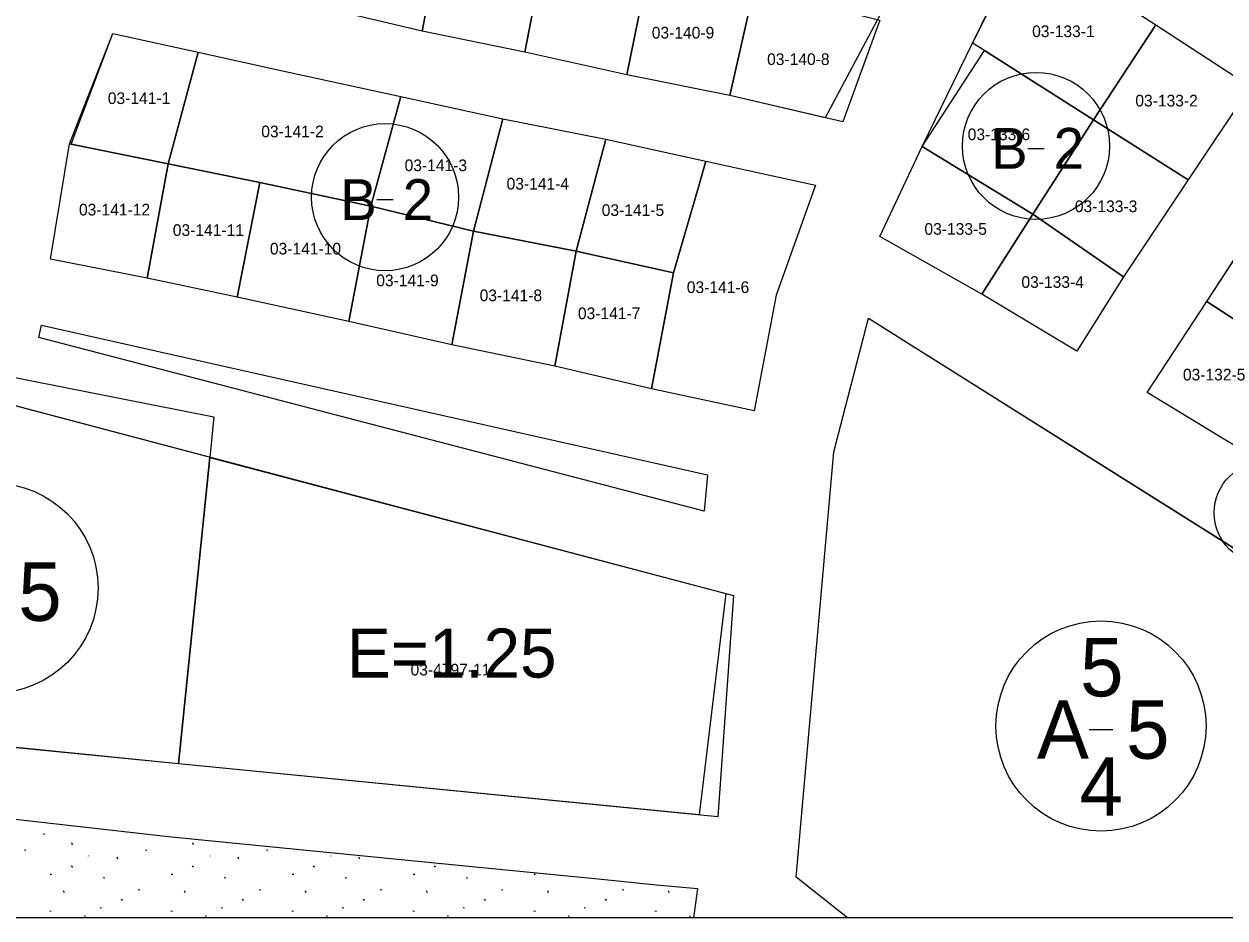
# Model space of a CAD drawing. Extents: x 413946 to 415528, y 4453939 to 4454944.
# Drawn here: x 414871.3 to 414974.2, y 4453939.5 to 4454016.1 of the extents above; entities that cross this region are included whole.
import ezdxf

# ---------------------------------------------------------------- set-up
doc = ezdxf.new("R2010")
doc.units = 0
for name, color, linetype in [('0_KADASTRO', 7, 'Continuous'), ('0_ÇERÇEVE', 7, 'Continuous'), ('Level 27', 7, 'Continuous'), ('Level 28', 7, 'Continuous'), ('Level 41', 7, 'Continuous'), ('Level 54', 7, 'Continuous'), ('Level 62', 7, 'Continuous'), ('SEMBOL', 7, 'Continuous')]:
    doc.layers.add(name, color=color, linetype=linetype)

msp = doc.modelspace()

# ---------------------------------------------------------------- linework, layer by layer
at = {"layer": '0_KADASTRO'}
for points in [[(414896.58, 4454017.51), (414898.64, 4454028.11), (414900.43, 4454027.65), (414907.43, 4454025.87), (414905.42, 4454015.45)], [(414905.42, 4454015.45), (414907.43, 4454025.87), (414909.43, 4454025.36), (414916.17, 4454023.65), (414914.21, 4454013.64)], [(414914.21, 4454013.64), (414916.17, 4454023.65), (414918.06, 4454023.17), (414924.92, 4454021.42), (414922.95, 4454011.69)], [(414952.58, 4454014.42), (414956.96, 4454023.35), (414968.29, 4454015.97), (414962.95, 4454007.85), (414953.6, 4454013.78)], [(414922.95, 4454011.69), (414924.92, 4454021.42), (414926.87, 4454020.92), (414933.86, 4454019.14), (414931.8, 4454009.93)], [(414931.8, 4454009.93), (414933.86, 4454019.14), (414935.82, 4454018.64), (414944.64, 4454016.39), (414941.47, 4454007.67)], [(414962.95, 4454007.85), (414968.29, 4454015.97), (414976.39, 4454010.71), (414971.06, 4454002.71)], [(414875.35, 4454005.76), (414878.91, 4454015.23), (414886.23, 4454013.64), (414883.67, 4454004.08)], [(414883.67, 4454004.08), (414886.23, 4454013.64), (414893.45, 4454012.04), (414903.6, 4454009.83), (414901.03, 4454000.45), (414891.51, 4454002.49)], [(414948.26, 4454005.56), (414953.6, 4454013.78), (414962.95, 4454007.85), (414957.76, 4453999.76)], [(414901.03, 4454000.45), (414903.6, 4454009.83), (414912.33, 4454007.92), (414909.83, 4453998.32)], [(414909.83, 4453998.32), (414912.33, 4454007.92), (414921.15, 4454006.18), (414918.63, 4453996.59)], [(414957.76, 4453999.76), (414962.95, 4454007.85), (414971.06, 4454002.71), (414965.53, 4453994.41)], [(414873.59, 4453995.9), (414875.22, 4454005.78), (414875.35, 4454005.76), (414883.67, 4454004.08), (414881.86, 4453994.27)], [(414918.63, 4453996.59), (414921.15, 4454006.18), (414929.73, 4454004.3), (414929.06, 4454001.99), (414926.97, 4453994.75)], [(414944.65, 4453997.84), (414948.26, 4454005.56), (414957.76, 4453999.76), (414953.37, 4453992.92)], [(414881.86, 4453994.27), (414883.67, 4454004.08), (414891.51, 4454002.49), (414889.57, 4453992.65)], [(414925.08, 4453984.8), (414926.97, 4453994.75), (414929.06, 4454001.99), (414929.73, 4454004.3), (414939.12, 4454002.24), (414935.76, 4453992.82), (414933.86, 4453982.93)], [(414889.57, 4453992.65), (414891.51, 4454002.49), (414901.03, 4454000.45), (414899.15, 4453990.57)], [(414899.15, 4453990.57), (414901.03, 4454000.45), (414909.83, 4453998.32), (414907.96, 4453988.58)], [(414953.37, 4453992.92), (414957.76, 4453999.76), (414965.53, 4453994.41), (414961.52, 4453988.03)], [(414972.65, 4453992.28), (414976.98, 4453998.9), (414984.98, 4453993.76), (414980.63, 4453987.09)], [(414907.96, 4453988.58), (414909.83, 4453998.32), (414918.63, 4453996.59), (414916.78, 4453986.75)], [(414916.78, 4453986.75), (414918.63, 4453996.59), (414926.97, 4453994.75), (414925.08, 4453984.8)], [(414967.55, 4453984.5), (414972.65, 4453992.28), (414980.63, 4453987.09), (414975.77, 4453979.48)], [(414847.64, 4453956.4), (414847.89, 4453969.56), (414848.25, 4453989.16), (414848.27, 4453990.17), (414887.57, 4453982.39), (414887.22, 4453978.91), (414884.55, 4453952.69)], [(414884.55, 4453952.69), (414887.22, 4453978.91), (414932.09, 4453967.11), (414930.77, 4453948.14)]]:
    msp.add_lwpolyline(points, close=True, dxfattribs=at)
for points in [[(414941.88, 4453939.48), (414937.48, 4453942.98), (414940.69, 4453979.42), (414943.68, 4453990.85), (415025.26, 4453939.48)], [(415025.26, 4453939.48), (414941.88, 4453939.48)]]:
    msp.add_lwpolyline(points, dxfattribs=at)
at = {"layer": '0_ÇERÇEVE'}
msp.add_lwpolyline([(413945.57, 4454943.96), (415494.14, 4454943.96), (415494.14, 4453939.48), (413945.57, 4453939.48)], close=True, dxfattribs=at)
at = {"layer": 'Level 27'}
for p, q in [((414952.58, 4454014.42), (414957.05, 4454023.31)), ((414956.96, 4454023.35), (414968.29, 4454015.97)), ((414905.42, 4454015.45), (414896.58, 4454017.51)), ((414944.62, 4454016.75), (414939.96, 4454008.02)), ((414968.29, 4454015.97), (414976.39, 4454010.71)), ((414875.22, 4454005.78), (414878.91, 4454015.23)), ((414878.91, 4454015.23), (414886.23, 4454013.64)), ((414914.21, 4454013.64), (414905.42, 4454015.45)), ((414948.26, 4454005.56), (414952.58, 4454014.42)), ((414886.23, 4454013.64), (414893.45, 4454012.04)), ((414922.95, 4454011.69), (414914.21, 4454013.64)), ((414893.45, 4454012.04), (414903.6, 4454009.83)), ((414931.8, 4454009.93), (414922.95, 4454011.69)), ((414903.6, 4454009.83), (414912.33, 4454007.92)), ((414939.96, 4454008.02), (414931.8, 4454009.93)), ((414976.39, 4454010.71), (414971.06, 4454002.71)), ((414912.33, 4454007.92), (414921.15, 4454006.18)), ((414873.59, 4453995.9), (414875.22, 4454005.78)), ((414921.15, 4454006.18), (414929.73, 4454004.3)), ((414944.65, 4453997.84), (414948.26, 4454005.56)), ((414929.73, 4454004.3), (414939.12, 4454002.24)), ((414971.06, 4454002.71), (414965.53, 4453994.41)), ((414939.12, 4454002.24), (414935.76, 4453992.82)), ((414972.65, 4453992.28), (414976.98, 4453998.9)), ((414953.37, 4453992.92), (414944.65, 4453997.84)), ((414881.86, 4453994.27), (414873.59, 4453995.9)), ((414889.57, 4453992.65), (414881.86, 4453994.27)), ((414965.53, 4453994.41), (414961.52, 4453988.03)), ((414899.15, 4453990.57), (414889.57, 4453992.65)), ((414935.76, 4453992.82), (414933.86, 4453982.93)), ((414961.52, 4453988.03), (414953.37, 4453992.92)), ((414967.55, 4453984.5), (414972.65, 4453992.28)), ((414907.96, 4453988.58), (414899.15, 4453990.57)), ((414916.78, 4453986.75), (414907.96, 4453988.58)), ((414925.08, 4453984.8), (414916.78, 4453986.75)), ((414933.86, 4453982.93), (414925.08, 4453984.8)), ((414975.77, 4453979.48), (414967.55, 4453984.5))]:
    msp.add_line(p, q, dxfattribs=at)
at = {"layer": 'Level 28'}
for p, q in [((414940.69, 4453979.42), (414943.68, 4453990.85)), ((414943.68, 4453990.85), (415025.41, 4453939.48)), ((414848.25, 4453989.27), (414931.45, 4453967.27)), ((414937.48, 4453942.98), (414940.69, 4453979.42)), ((414931.45, 4453967.27), (414929.15, 4453948.3)), ((414884.55, 4453952.69), (414849.79, 4453956.12)), ((414929.15, 4453948.3), (414884.55, 4453952.69)), ((414847.54, 4453950.57), (414883.94, 4453946.43)), ((414883.94, 4453946.43), (414910.57, 4453943.8)), ((414910.57, 4453943.8), (414920.52, 4453942.82)), ((414920.52, 4453942.82), (414925.49, 4453942.33)), ((414941.88, 4453939.48), (414937.48, 4453942.98)), ((414925.49, 4453942.33), (414929.03, 4453942.01)), ((414929.03, 4453942.01), (414928.67, 4453939.48))]:
    msp.add_line(p, q, dxfattribs=at)
at = {"layer": 'Level 41'}
for p, q in [((414871.63, 4453947.81), (414871.62, 4453947.83)), ((414871.63, 4453947.81), (414871.62, 4453947.83)), ((414878.96, 4453946.9), (414878.92, 4453947)), ((414878.96, 4453946.9), (414878.92, 4453947)), ((414872.94, 4453946.68), (414873.07, 4453946.65)), ((414872.94, 4453946.68), (414873.07, 4453946.65)), ((414875.47, 4453945.75), (414875.4, 4453945.91)), ((414875.47, 4453945.75), (414875.4, 4453945.91)), ((414885.83, 4453945.75), (414885.77, 4453945.91)), ((414885.83, 4453945.75), (414885.77, 4453945.91)), ((414871.34, 4453945.31), (414871.47, 4453945.29)), ((414871.34, 4453945.31), (414871.47, 4453945.29)), ((414881.71, 4453945.31), (414881.83, 4453945.29)), ((414881.71, 4453945.31), (414881.83, 4453945.29)), ((414892.08, 4453945.31), (414892.2, 4453945.29)), ((414892.08, 4453945.31), (414892.2, 4453945.29)), ((414875.35, 4453943.95), (414875.48, 4453943.85)), ((414875.35, 4453943.95), (414875.48, 4453943.85)), ((414876.82, 4453944.79), (414876.83, 4453944.78)), ((414876.82, 4453944.79), (414876.83, 4453944.78)), ((414879.34, 4453944.52), (414879.28, 4453944.68)), ((414879.34, 4453944.52), (414879.28, 4453944.68)), ((414885.72, 4453943.95), (414885.84, 4453943.85)), ((414885.72, 4453943.95), (414885.84, 4453943.85)), ((414887.19, 4453944.79), (414887.2, 4453944.78)), ((414887.19, 4453944.79), (414887.2, 4453944.78)), ((414889.71, 4453944.52), (414889.65, 4453944.68)), ((414889.71, 4453944.52), (414889.65, 4453944.68)), ((414896.08, 4453943.95), (414896.21, 4453943.85)), ((414896.08, 4453943.95), (414896.21, 4453943.85)), ((414897.56, 4453944.79), (414897.57, 4453944.78)), ((414897.56, 4453944.79), (414897.57, 4453944.78)), ((414900.08, 4453944.52), (414900.01, 4453944.68)), ((414900.08, 4453944.52), (414900.01, 4453944.68)), ((414906.45, 4453943.95), (414906.58, 4453943.85)), ((414906.45, 4453943.95), (414906.58, 4453943.85)), ((414873.56, 4453943.24), (414873.68, 4453943.22)), ((414873.56, 4453943.24), (414873.68, 4453943.22)), ((414878.1, 4453942.95), (414878.23, 4453942.92)), ((414878.1, 4453942.95), (414878.23, 4453942.92)), ((414883.92, 4453943.24), (414884.05, 4453943.22)), ((414883.92, 4453943.24), (414884.05, 4453943.22)), ((414888.47, 4453942.95), (414888.6, 4453942.92)), ((414888.47, 4453942.95), (414888.6, 4453942.92)), ((414894.29, 4453943.24), (414894.42, 4453943.22)), ((414894.29, 4453943.24), (414894.42, 4453943.22)), ((414898.84, 4453942.95), (414898.97, 4453942.92)), ((414898.84, 4453942.95), (414898.97, 4453942.92)), ((414904.66, 4453943.24), (414904.79, 4453943.22)), ((414904.66, 4453943.24), (414904.79, 4453943.22)), ((414909.21, 4453942.95), (414909.33, 4453942.92)), ((414909.21, 4453942.95), (414909.33, 4453942.92)), ((414915.03, 4453943.24), (414915.15, 4453943.22)), ((414915.03, 4453943.24), (414915.15, 4453943.22)), ((414874.77, 4453941.64), (414874.7, 4453941.81)), ((414874.77, 4453941.64), (414874.7, 4453941.81)), ((414881.1, 4453941.92), (414881.23, 4453941.9)), ((414881.1, 4453941.92), (414881.23, 4453941.9)), ((414885.14, 4453941.64), (414885.07, 4453941.81)), ((414885.14, 4453941.64), (414885.07, 4453941.81)), ((414891.47, 4453941.92), (414891.6, 4453941.9)), ((414891.47, 4453941.92), (414891.6, 4453941.9)), ((414895.5, 4453941.64), (414895.44, 4453941.81)), ((414895.5, 4453941.64), (414895.44, 4453941.81)), ((414901.84, 4453941.92), (414901.96, 4453941.9)), ((414901.84, 4453941.92), (414901.96, 4453941.9)), ((414905.87, 4453941.64), (414905.81, 4453941.81)), ((414905.87, 4453941.64), (414905.81, 4453941.81)), ((414912.21, 4453941.92), (414912.33, 4453941.9)), ((414912.21, 4453941.92), (414912.33, 4453941.9)), ((414916.24, 4453941.64), (414916.18, 4453941.81)), ((414916.24, 4453941.64), (414916.18, 4453941.81)), ((414922.57, 4453941.92), (414922.7, 4453941.9)), ((414922.57, 4453941.92), (414922.7, 4453941.9)), ((414926.61, 4453941.64), (414926.54, 4453941.81)), ((414926.61, 4453941.64), (414926.54, 4453941.81)), ((414879.63, 4453941.09), (414879.76, 4453940.99)), ((414879.63, 4453941.09), (414879.76, 4453940.99)), ((414890, 4453941.09), (414890.12, 4453940.99)), ((414890, 4453941.09), (414890.12, 4453940.99)), ((414900.36, 4453941.09), (414900.49, 4453940.99)), ((414900.36, 4453941.09), (414900.49, 4453940.99)), ((414910.73, 4453941.09), (414910.86, 4453940.99)), ((414910.73, 4453941.09), (414910.86, 4453940.99)), ((414921.1, 4453941.09), (414921.23, 4453940.99)), ((414921.1, 4453941.09), (414921.23, 4453940.99)), ((414873.53, 4453940.08), (414873.65, 4453940.05)), ((414873.53, 4453940.08), (414873.65, 4453940.05)), ((414877.83, 4453940.38), (414877.96, 4453940.36)), ((414877.83, 4453940.38), (414877.96, 4453940.36)), ((414883.9, 4453940.08), (414884.02, 4453940.05)), ((414883.9, 4453940.08), (414884.02, 4453940.05)), ((414888.2, 4453940.38), (414888.33, 4453940.36)), ((414888.2, 4453940.38), (414888.33, 4453940.36)), ((414894.26, 4453940.08), (414894.39, 4453940.05)), ((414894.26, 4453940.08), (414894.39, 4453940.05)), ((414898.57, 4453940.38), (414898.7, 4453940.36)), ((414898.57, 4453940.38), (414898.7, 4453940.36)), ((414904.63, 4453940.08), (414904.76, 4453940.05)), ((414904.63, 4453940.08), (414904.76, 4453940.05)), ((414908.94, 4453940.38), (414909.06, 4453940.36)), ((414908.94, 4453940.38), (414909.06, 4453940.36)), ((414915, 4453940.08), (414915.13, 4453940.05)), ((414915, 4453940.08), (414915.13, 4453940.05)), ((414919.31, 4453940.38), (414919.43, 4453940.36)), ((414919.31, 4453940.38), (414919.43, 4453940.36)), ((414925.37, 4453940.08), (414925.49, 4453940.05)), ((414925.37, 4453940.08), (414925.49, 4453940.05)), ((414876.46, 4453939.67), (414876.58, 4453939.64)), ((414876.46, 4453939.67), (414876.58, 4453939.64)), ((414886.83, 4453939.67), (414886.95, 4453939.64)), ((414886.83, 4453939.67), (414886.95, 4453939.64)), ((414897.19, 4453939.67), (414897.32, 4453939.64)), ((414897.19, 4453939.67), (414897.32, 4453939.64)), ((414907.56, 4453939.67), (414907.69, 4453939.64)), ((414907.56, 4453939.67), (414907.69, 4453939.64)), ((414917.93, 4453939.67), (414918.06, 4453939.64)), ((414917.93, 4453939.67), (414918.06, 4453939.64)), ((414928.3, 4453939.67), (414928.42, 4453939.64)), ((414928.3, 4453939.67), (414928.42, 4453939.64))]:
    msp.add_line(p, q, dxfattribs=at)
at = {"layer": 'Level 54'}
for points in [[(414931.8, 4454009.93), (414922.95, 4454011.69), (414914.21, 4454013.64), (414905.42, 4454015.45), (414896.58, 4454017.51), (414887.69, 4454019.48), (414879.55, 4454021.32), (414881.85, 4454032.39), (414884.75, 4454044.87), (414895.34, 4454041.69), (414895.55, 4454042.26), (414904.24, 4454039.58), (414912.8, 4454036.89), (414921.56, 4454034.01), (414930.08, 4454031.32), (414938.56, 4454028.53), (414949.02, 4454025.14), (414944.62, 4454016.75), (414939.96, 4454008.02)], [(414944.65, 4453997.84), (414948.26, 4454005.56), (414952.58, 4454014.42), (414956.96, 4454023.35), (414968.29, 4454015.97), (414976.39, 4454010.71), (414971.06, 4454002.71), (414965.53, 4453994.41), (414961.52, 4453988.03), (414953.37, 4453992.92)], [(414935.76, 4453992.82), (414933.86, 4453982.93), (414925.08, 4453984.8), (414916.78, 4453986.75), (414907.96, 4453988.58), (414899.15, 4453990.57), (414889.57, 4453992.65), (414881.86, 4453994.27), (414873.59, 4453995.9), (414873.59, 4453995.9), (414875.22, 4454005.78), (414878.91, 4454015.23), (414886.23, 4454013.64), (414893.45, 4454012.04), (414903.6, 4454009.83), (414912.33, 4454007.92), (414921.15, 4454006.18), (414929.73, 4454004.3), (414939.12, 4454002.24)], [(414992.9, 4453988.68), (414988.67, 4453981.94), (414984.11, 4453974.71), (414975.77, 4453979.48), (414967.55, 4453984.5), (414972.65, 4453992.28), (414976.98, 4453998.9), (414982.03, 4454006.91), (414990.06, 4454001.81), (414997.93, 4453996.69)], [(414847.64, 4453956.33), (414848.25, 4453989.27), (414931.45, 4453967.27), (414929.15, 4453948.3), (414884.55, 4453952.69), (414849.79, 4453956.12)]]:
    msp.add_lwpolyline(points, close=True, dxfattribs=at)
for points in [[(414941.88, 4453939.48), (414937.48, 4453942.98), (414940.69, 4453979.42), (414943.68, 4453990.85), (415025.41, 4453939.48)], [(415025.41, 4453939.48), (414941.88, 4453939.48)]]:
    msp.add_lwpolyline(points, dxfattribs=at)
at = {"layer": 'Level 62'}
msp.add_lwpolyline([(414872.8, 4453990.26), (414929.86, 4453977.45), (414929.59, 4453974.32), (414872.57, 4453989.2), (414872.8, 4453990.26)], dxfattribs=at)
at = {"layer": 'SEMBOL'}
for p, q in [((414957.32, 4454005.4), (414958.72, 4454005.4)), ((414901.55, 4454001.01), (414902.95, 4454001.01)), ((414962.59, 4453955.62), (414964.59, 4453955.62))]:
    msp.add_line(p, q, dxfattribs=at)
for centre, radius in [((414958.02, 4454005.61), 6.3), ((414902.25, 4454001.22), 6.3), ((414977.67, 4453974.18), 4.38), ((414868.66, 4453967.73), 9), ((414963.59, 4453955.92), 9)]:
    msp.add_circle(centre, radius, dxfattribs=at)

# ---------------------------------------------------------------- texts
at = {"layer": '0_KADASTRO'}
for s, p in [('03-133-1', (414957.69, 4454014.93)), ('03-140-9', (414925.1, 4454014.81)), ('03-140-8', (414934.98, 4454012.54)), ('03-141-1', (414878.49, 4454009.2)), ('03-133-2', (414966.53, 4454008.99)), ('03-141-2', (414891.64, 4454006.35)), ('03-133-6', (414952.17, 4454006.1)), ('03-141-3', (414903.92, 4454003.45)), ('03-141-4', (414912.66, 4454001.87)), ('03-141-12', (414876.02, 4453999.65)), ('03-141-5', (414920.81, 4453999.61)), ('03-133-3', (414961.35, 4453999.94)), ('03-141-11', (414884.06, 4453997.9)), ('03-133-5', (414948.46, 4453998)), ('03-141-10', (414892.38, 4453996.31)), ('03-141-9', (414901.49, 4453993.59)), ('03-133-4', (414956.77, 4453993.45)), ('03-141-8', (414910.35, 4453992.31)), ('03-141-6', (414928.1, 4453993.01)), ('03-141-7', (414918.77, 4453990.77)), ('03-132-5', (414970.61, 4453985.52)), ('03-4797-11', (414904.43, 4453960.25))]:
    msp.add_text(s, height=1, dxfattribs=at).set_placement(p)
at = {"layer": 'SEMBOL'}
for s, height, p in [('B', 3.5, (414954.18, 4454003.65)), ('2', 3.5, (414959.53, 4454003.65)), ('B', 3.5, (414898.41, 4453999.26)), ('2', 3.5, (414903.76, 4453999.26)), ('5', 5, (414870.82, 4453964.93)), ('E=1.25', 4.2, (414898.98, 4453960.07)), ('5', 5, (414961.8, 4453958.46)), ('A', 5, (414958.1, 4453953.12)), ('5', 5, (414965.74, 4453953.12)), ('4', 5, (414961.75, 4453948.25))]:
    msp.add_text(s, height=height, dxfattribs=at).set_placement(p)

doc.saveas('drawing.dxf')
